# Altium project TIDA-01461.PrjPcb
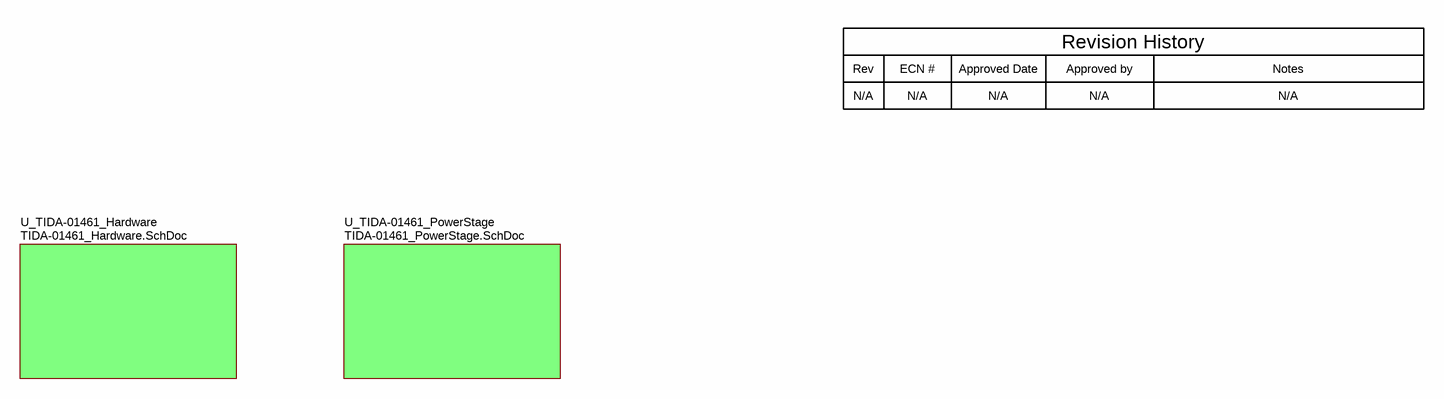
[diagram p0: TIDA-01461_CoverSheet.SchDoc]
CopyrightYear: 2017; PCB_Layout: Tobias Puetz; PCB_Rev: E1; PRJ_Customer: Public Release; PRJ_Engineer: Tobias Puetz; PRJ_Number: TIDA-01461; PRJ_Title: EtherCAT P – One cable for power and EtherCAT Reference Design; SCH_Rev: E1; TechSupport: http://www.ti.com/support; TID: TIDA-01461
6 sheets, 151 parts. Net scope: strictly hierarchical (ports join the sheet entries above them; power ports are local).
Board file: TIDA-01461_PCB.PcbDoc
Sheets:
  TIDA-01461_CoverSheet.SchDoc
    U_TIDA-01461_Hardware = TIDA-01461_Hardware.SchDoc
    U_TIDA-01461_PowerStage = TIDA-01461_PowerStage.SchDoc
      Up = TIDA-01461_PowerInputProtection.SchDoc
      Us = TIDA-01461_PowerInputProtection.SchDoc
      Buck = TIDA-01461_Buck.SchDoc
      TVS3300_Us = TIDA-01461_TVS3300.SchDoc
      TVS3300_Up = TIDA-01461_TVS3300.SchDoc

## Sheet TIDA-01461_CoverSheet.SchDoc: CoverSheet
size 431 x 279 mm; Date: Not shown in title block; ApprovedBy: Not shown in title block; CheckedBy: Not shown in title block; Author: Not shown in title block; CompanyName: Not shown in title block; DrawnBy: Tobias Puetz; Engineer: Not shown in title block; Organization: Not shown in title block; Address1: Not shown in title block; Address2: Not shown in title block; Address3: Not shown in title block; Address4: Not shown in title block; DocumentNumber: 1; Revision: Use project parameter SCH_Rev; SheetNumber: 1; SheetTotal: 6; PageSetup: Record=PageOptions¦CenterHorizontal=True¦CenterVertical=True¦PrintScale=1.00¦XCorrection=1.00¦YCorrection=1.00¦PrintKind=0¦BorderSize=5000000¦LeftOffset=0¦BottomOffset=0¦Orientation=2¦PaperLength=1000¦PaperWidth=1000¦Scale=100¦PaperSource=15¦PrintQuality=600¦MediaType=1¦DitherType=10¦PaperKind=Letter¦PrintScaleMode=1

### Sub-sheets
U_TIDA-01461_Hardware = TIDA-01461_Hardware.SchDoc: no entries
U_TIDA-01461_PowerStage = TIDA-01461_PowerStage.SchDoc: no entries

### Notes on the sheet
- Rev
- N/A
- ECN #
- Approved Date
- Approved by
- Revision History
- Notes

## Sheet TIDA-01461_Hardware.SchDoc: Hardware
size 431 x 279 mm; Date: Not shown in title block; ApprovedBy: Not shown in title block; CheckedBy: Not shown in title block; Author: Not shown in title block; CompanyName: Not shown in title block; DrawnBy: Tobias Puetz; Engineer: Not shown in title block; Organization: Not shown in title block; Address1: Not shown in title block; Address2: Not shown in title block; Address3: Not shown in title block; Address4: Not shown in title block; DocumentNumber: 2; Revision: Use project parameter SCH_Rev; SheetNumber: 2; SheetTotal: 6; PageSetup: Record=PageOptions¦CenterHorizontal=True¦CenterVertical=True¦PrintScale=1.00¦XCorrection=1.00¦YCorrection=1.00¦PrintKind=0¦BorderSize=5000000¦LeftOffset=0¦BottomOffset=0¦Orientation=2¦PaperLength=1000¦PaperWidth=1000¦Scale=100¦PaperSource=15¦PrintQuality=600¦MediaType=1¦DitherType=10¦PaperKind=Letter¦PrintScaleMode=1
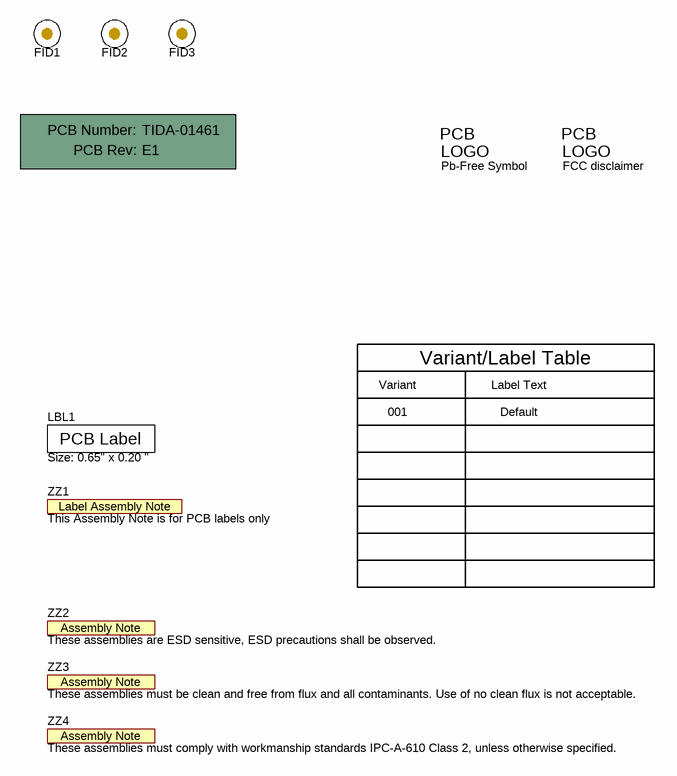
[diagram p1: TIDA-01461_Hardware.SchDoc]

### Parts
!PCB1  Printed Circuit Board  (value not drawn)  (mechanical)
FID1  Fiducial  [Fiducial10-20]  (value not drawn)
FID2  Fiducial  [Fiducial10-20]  (value not drawn)
FID3  Fiducial  [Fiducial10-20]  (value not drawn)
LBL1  Size: 0.65" x 0.20 "  [Label_650x200]
Logo1  Pb-Free Symbol  [Pb-Free_Overlay_Small]  (no BOM)
Logo2  FCC disclaimer  [FCC_disclaimer]  (no BOM)
ZZ1  This Assembly Note is for PCB labels only  [AssemblyNoteLabel]  (no BOM)
ZZ2  These assemblies are ESD sensitive, ESD precautions shall be observed.  [AssemblyNote]  (no BOM)
ZZ3  These assemblies must be clean and free from flux and all contaminants. Use of no clean flux is not acceptable.  [AssemblyNote]  (no BOM)
ZZ4  These assemblies must comply with workmanship standards IPC-A-610 Class 2, unless otherwise specified.  [AssemblyNote]  (no BOM)

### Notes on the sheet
- Variant
- Variant/Label Table
- Label Text
- 001
- Default

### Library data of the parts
!PCB1 = PCB: Manufacturer: Any; PartNumber: TIDA-01461; SymbolCreator: a0412235
FID1-FID3 = Fiducial: Fiducial mark.  There is nothing to buy or mount.; SymbolCreator: codlsc
LBL1 = THT-14-423-10: Thermal Transfer Printable Labels, 0.650" W x 0.200" H - 10,000 per roll; Manufacturer: Brady; SymbolCreator: a0412235; CompType: Label
Logo1 = Pb-Free: SymbolCreator: a0412235
Logo2 = FCC_disclaimer: SymbolCreator: codlsc
ZZ1 = AssemblyNoteLabel: SymbolCreator: a0412235
ZZ2-ZZ4 = AssemblyNote: SymbolCreator: codlsc

## Sheet TIDA-01461_PowerStage.SchDoc: PowerStage
size 431 x 279 mm; Date: Not shown in title block; ApprovedBy: Not shown in title block; CheckedBy: Not shown in title block; Author: Not shown in title block; CompanyName: Not shown in title block; DrawnBy: Tobias Puetz; Engineer: Not shown in title block; Organization: Not shown in title block; Address1: Not shown in title block; Address2: Not shown in title block; Address3: Not shown in title block; Address4: Not shown in title block; DocumentNumber: 3; Revision: Use project parameter SCH_Rev; SheetNumber: 3; SheetTotal: 6; PageSetup: Record=PageOptions¦CenterHorizontal=True¦CenterVertical=True¦PrintScale=1.00¦XCorrection=1.00¦YCorrection=1.00¦PrintKind=0¦BorderSize=5000000¦LeftOffset=0¦BottomOffset=0¦Orientation=2¦PaperLength=1000¦PaperWidth=1000¦Scale=100¦PaperSource=15¦PrintQuality=600¦MediaType=1¦DitherType=10¦PaperKind=Letter¦PrintScaleMode=1
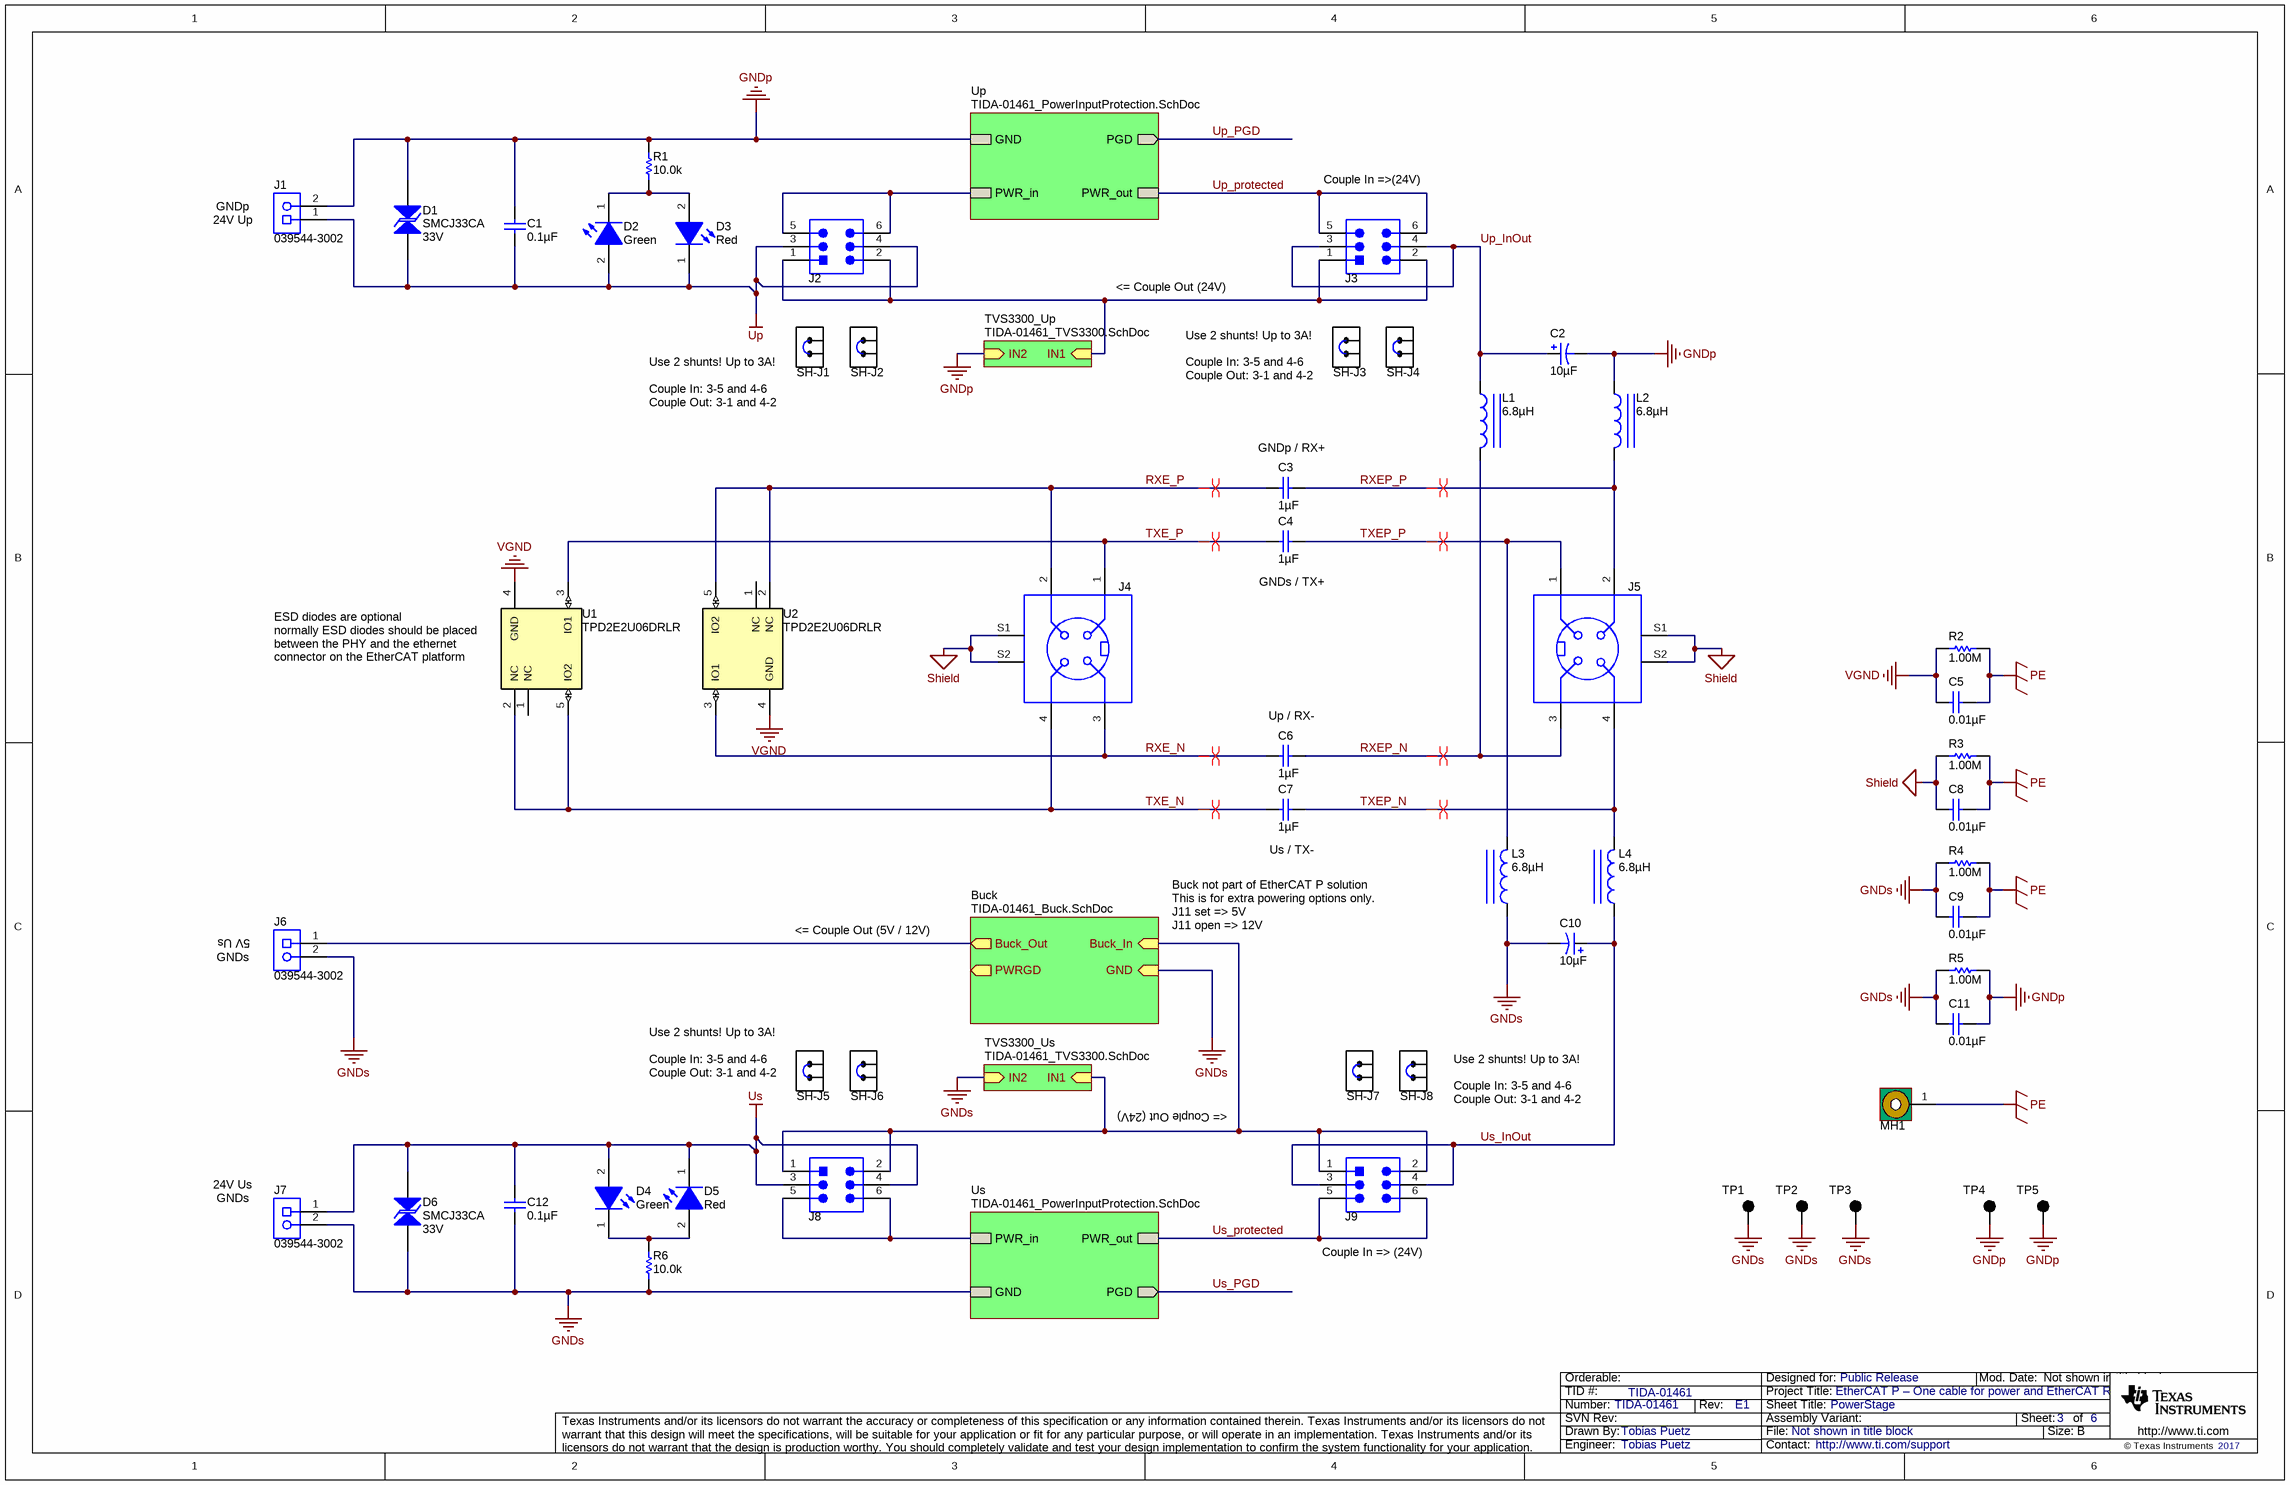
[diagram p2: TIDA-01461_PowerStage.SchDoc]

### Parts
C1  ValueDisplayed: 0.1µF  [1206]  (hidden comment: GRM319R72A104KA01D)
C2  ValueDisplayed: 10µF  [3528-21]  (hidden comment: TCJB106M035R0200)
C3  ValueDisplayed: 1µF  [1206_180]  (hidden comment: GRM31CR72A105KA01L)
C4  ValueDisplayed: 1µF  [1206_180]  (hidden comment: GRM31CR72A105KA01L)
C5  ValueDisplayed: 0.01µF  [1206]  (hidden comment: VJ1206Y103KXEAT5Z)
C6  ValueDisplayed: 1µF  [1206_180]  (hidden comment: GRM31CR72A105KA01L)
C7  ValueDisplayed: 1µF  [1206_180]  (hidden comment: GRM31CR72A105KA01L)
C8  ValueDisplayed: 0.01µF  [1206]  (hidden comment: VJ1206Y103KXEAT5Z)
C9  ValueDisplayed: 0.01µF  [1206]  (hidden comment: VJ1206Y103KXEAT5Z)
C10  ValueDisplayed: 10µF  [3528-21]  (hidden comment: TCJB106M035R0200)
C11  ValueDisplayed: 0.01µF  [1206]  (hidden comment: VJ1206Y103KXEAT5Z)
C12  ValueDisplayed: 0.1µF  [1206]  (hidden comment: GRM319R72A104KA01D)
D1  SMCJ33CA  value 33V  [SMC]
D2  value Green  [WL-SMCW_GREEN]  (hidden comment: 150060GS75000)
D3  value Red  [WL-SMCW_RED]  (hidden comment: 150060RS75000)
D4  value Green  [WL-SMCW_GREEN]  (hidden comment: 150060GS75000)
D5  value Red  [WL-SMCW_RED]  (hidden comment: 150060RS75000)
D6  SMCJ33CA  value 33V  [SMC]
J1  039544-3002  [Molex_039544-3002]
J2  61300621121  [Wurth_61300621121]  (value not drawn)
J3  61300621121  [Wurth_61300621121]  (value not drawn)
J4  09 3420 81 04  [Binder_09_3420_81_04]  (value not drawn)
J5  ZS7002-0001  [Beckhoff_ZS7002-0001]  (value not drawn)
J6  039544-3002  [Molex_039544-3002]
J7  039544-3002  [Molex_039544-3002]
J8  61300621121  [Wurth_61300621121]  (value not drawn)
J9  61300621121  [Wurth_61300621121]  (value not drawn)
L1  ValueDisplayed: 6.8µH  [WE-LHMI_7030]  (hidden comment: 74437346068)
L2  ValueDisplayed: 6.8µH  [WE-LHMI_7030]  (hidden comment: 74437346068)
L3  ValueDisplayed: 6.8µH  [WE-LHMI_7030]  (hidden comment: 74437346068)
L4  ValueDisplayed: 6.8µH  [WE-LHMI_7030]  (hidden comment: 74437346068)
MH1  MTG_Pads  [MTGP_4-40_PanHead]  (value not drawn)  (no BOM)
R1  ValueDisplayed: 10.0k  [0603]  (hidden comment: CRCW060310K0FKEA)
R2  ValueDisplayed: 1.00M  [1206]  (hidden comment: CRCW12061M00FKEA)
R3  ValueDisplayed: 1.00M  [1206]  (hidden comment: CRCW12061M00FKEA)
R4  ValueDisplayed: 1.00M  [1206]  (hidden comment: CRCW12061M00FKEA)
R5  ValueDisplayed: 1.00M  [1206]  (hidden comment: CRCW12061M00FKEA)
R6  ValueDisplayed: 10.0k  [0603]  (hidden comment: CRCW060310K0FKEA)
SH-J1  60900213421  [Wurth_60900213421]  (value not drawn)
SH-J2  60900213421  [Wurth_60900213421]  (value not drawn)
SH-J3  60900213421  [Wurth_60900213421]  (value not drawn)
SH-J4  60900213421  [Wurth_60900213421]  (value not drawn)
SH-J5  60900213421  [Wurth_60900213421]  (value not drawn)
SH-J6  60900213421  [Wurth_60900213421]  (value not drawn)
SH-J7  60900213421  [Wurth_60900213421]  (value not drawn)
SH-J8  60900213421  [Wurth_60900213421]  (value not drawn)
TP1  5001  [Keystone5001]  (value not drawn)
TP2  5001  [Keystone5001]  (value not drawn)
TP3  5001  [Keystone5001]  (value not drawn)
TP4  5001  [Keystone5001]  (value not drawn)
TP5  5001  [Keystone5001]  (value not drawn)
U1  TPD2E2U06DRLR  [DRL0005A]
U2  TPD2E2U06DRLR  [DRL0005A]

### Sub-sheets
Buck = TIDA-01461_Buck.SchDoc: Buck_Out (out), Buck_In (in), GND (in), PWRGD (out)
TVS3300_Up = TIDA-01461_TVS3300.SchDoc: IN2 (in), IN1 (in)
TVS3300_Us = TIDA-01461_TVS3300.SchDoc: IN2 (in), IN1 (in)
Up = TIDA-01461_PowerInputProtection.SchDoc: PGD (out), PWR_in, PWR_out, GND
Us = TIDA-01461_PowerInputProtection.SchDoc: PGD (out), PWR_in, PWR_out, GND

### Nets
GNDp: C1.1 C2.2(-) C11.1 D1.2 J1.2 L2.1 R1.1 R5.2 TP4.1 TP5.1 ; sheet Up/GND, sheet TVS3300_Up/IN2  [project net GND]
GNDs: C9.2 C10.2(-) C11.2 C12.2 D6.1 J6.2 J7.2 L3.1 R4.1 R5.1 R6.2 TP1.1 TP2.1 TP3.1 ; sheet Us/GND, sheet Buck/GND, sheet TVS3300_Us/IN2  [project net GND]
PE: C5.1 C8.1 C9.1 MH1.1 R2.2 R3.2 R4.2
Shield: C8.2 J4.S1 J4.S2 J5.S1 J5.S2 R3.1
Up: C1.2 D1.1 D2.2(A) D3.1(K) J1.1 J2.3 J2.4
Us: C12.1 D4.2(A) D5.1(K) D6.2 J7.1 J8.3 J8.4
VGND: C5.2 R2.1 U1.4(GND) U2.4(GND)
Buck_In: J8.1 J8.2 J9.1 J9.2 ; sheet Buck/Buck_In, sheet TVS3300_Us/IN1
Buck_Out: J6.1 ; sheet Buck/Buck_Out
IN1: J2.1 J2.2 J3.1 J3.2 ; sheet TVS3300_Up/IN1
PWR_in: J8.5 J8.6 ; sheet Us/PWR_in
PWR_in: J2.5 J2.6 ; sheet Up/PWR_in  [a separate net that carries the same name]
RXE_N: C6.2 J4.3 U2.3(IO1)
RXE_P: C3.2 J4.2 U2.2(NC) U2.5(IO2)
RXEP_N: C6.1 J5.3 L1.2
RXEP_P: C3.1 J5.2 L2.2
TXE_N: C7.2 J4.4 U1.2(NC) U1.5(IO2)
TXE_P: C4.2 J4.1 U1.3(IO1)
TXEP_N: C7.1 J5.4 L4.2
TXEP_P: C4.1 J5.1 L3.2
Up_InOut: C2.1(+) J3.3 J3.4 L1.1
Up_protected: J3.5 J3.6 ; sheet Up/PWR_out
Us_InOut: C10.1(+) J9.3 J9.4 L4.1
Us_protected: J9.5 J9.6 ; sheet Us/PWR_out
NetD2_1: D2.1(K) D3.2(A) R1.2
NetD4_1: D4.1(K) D5.2(A) R6.1

Not connected (* = marked no-connect by the designer): U1 1(NC); U2 1(NC)

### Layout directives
differential pair: RXE_N, RXE_P, RXEP_N, RXEP_P, TXE_N, TXE_P, TXEP_N, TXEP_P

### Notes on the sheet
- (near J1) 24V Up
- GNDp
- (near J3) Couple In =>(24V)
- <= Couple Out (24V)
- (near SH-J1) Use 2 shunts! Up to 3A!
  Couple In: 3-5 and 4-6
  Couple Out: 3-1 and 4-2
- (near SH-J3) Use 2 shunts! Up to 3A!
  Couple In: 3-5 and 4-6
  Couple Out: 3-1 and 4-2
- (near C3) GNDp / RX+
- (near C4) GNDs / TX+
- (near U1) ESD diodes are optional
  normally ESD diodes should be placed between the PHY and the ethernet connector on the EtherCAT platform
- (near C6) Up / RX-
- (near C7) Us / TX-
- (near J6) 5V Us
- GNDs
- <= Couple Out (5V / 12V)
- Buck not part of EtherCAT P solution
  This is for extra powering options only.
  J11 set => 5V
  J11 open => 12V
- (near SH-J5) Use 2 shunts! Up to 3A!
  Couple In: 3-5 and 4-6
  Couple Out: 3-1 and 4-2
- (near SH-J8) Use 2 shunts! Up to 3A!
  Couple In: 3-5 and 4-6
  Couple Out: 3-1 and 4-2
- (near J7) 24V Us
- (near J9) Couple In => (24V)

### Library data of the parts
C1 C12 = GRM319R72A104KA01D: CAP, CERM, 0.1 µF, 100 V,+/- 10%, X7R, 1206; Manufacturer: MuRata; Polarized: N; CompType: Capacitor; Value: 0.1uF; U/M: EA; Cap_F: 0.0000001; Tolerance_%: 10; Value1: Unknown; VDC_V: 100; Value2: 100V; TaMin_C: -55; TaMax_C: 125; SizeArea_mm2: 5.12; SizeAreaWB_mm2: 10.92; SizeX_mm: 3.2; SizeY_mm: 1.6; SizeZ_mm: 1.35; AEC Category: Q200
C2 C10 = TCJB106M035R0200: CAP, Tantalum Polymer, 10 µF, 35 V,+/- 20%, 0.2 ohm, 3528-21 SMD; Manufacturer: AVX; Polarized: Y; CompType: Capacitor; Value: 10uF; U/M: EA; Cap_F: 0.00001; Tolerance_%: 20; Value1: 0.2 ohm; VDC_V: 35; Value2: 35V; ESR_ohm: 0.2; IRMS_A: 0.8; TaMin_C: -55; TaMax_C: 105; SizeAreaWB_mm2: 17.1; SizeArea_mm2: 9.8; SizeX_mm: 3.5; SizeY_mm: 2.8; SizeZ_mm: 2.1; AEC Category: Q200; AEC Qualified: N
C3 C4 C6 C7 = GRM31CR72A105KA01L: CAP, CERM, 1 µF, 100 V,+/- 10%, X7R, 1206; Manufacturer: MuRata; Polarized: N; CompType: Capacitor; Value: 1uF; U/M: EA; Cap_F: 0.000001; Tolerance_%: 10; Value1: Unknown; VDC_V: 100; Value2: 100V; TaMin_C: -55; TaMax_C: 125; Cap_Case: 1206; SizeArea_mm2: 5.12; SizeAreaWB_mm2: 10.92; SizeX_mm: 3.2; SizeY_mm: 1.6; SizeZ_mm: 1.8; AEC Category: Q200; Green_Lifecycle: Active; Green_REACh: Passed
C5 C8 C9 C11 = VJ1206Y103KXEAT5Z: CAP, CERM, 0.01 µF, 500 V,+/- 10%, X7R, 1206; Manufacturer: Vishay-Vitramon; Polarized: N; CompType: Capacitor; Value: 0.01uF; U/M: EA; Cap_F: 0.00000001; Tolerance_%: 10; VDC_V: 500; Value2: 500V; TaMin_C: -55; TaMax_C: 125; SizeArea_mm2: 5.12; SizeAreaWB_mm2: 10.92; SizeX_mm: 3.2; SizeY_mm: 1.6; SizeZ_mm: 1.35; AEC Category: Q200
D1 D6 = SMCJ33CA: Diode, TVS, Bi, 33 V, SMC; Manufacturer: Bourns; U/M: EA; Power_W: 5; Vr_V: 33; Value1: 5W; SizeAreaWB_mm2: 83.2686; SizeArea_mm2: 50.5686; SizeX_mm: 8.13; SizeY_mm: 6.22; SizeZ_mm: 2.6; AEC Category: Q101
D2 D4 = 150060GS75000: LED, Green, SMD; Manufacturer: Wurth Elektronik; Type: InGaN; Vf_V: 3.2; Value2: 3.2V; Io_A: 0.02; Tjmax_C: 85; Value1: W; Angle: 140; U/M: EA; Green_Lifecycle: Active; Green_REACh: Passed
D3 D5 = 150060RS75000: LED, Red, SMD; Manufacturer: Wurth Elektronik; Type: AlInGaP; Vf_V: 2; Value2: 2V; Io_A: 0.03; Vr_V: 5; Tjmax_C: 85; Power_TotalModule: 0.072; Value1: 0.072W; Angle: 140; U/M: EA; Green_Lifecycle: Active; Green_REACh: Passed
J1 J6 J7 = 039544-3002: Terminal Block, 5.08mm, 2x1, TH; Manufacturer: Molex; SymbolCreator: a0412235; Pitch_mm: 5.08; Gender: Female; Row_Count: 1; ContactFinish: Tin; Current_A: 15; Voltage_V: 300; Cert_UL: Y
J2 J3 J8 J9 = 61300621121: Header, 2.54mm, 3x2, Gold, TH; Manufacturer: Wurth Elektronik; SymbolCreator: a0412235; Pitch_mm: 2.54; Gender: Male; Shrouded: N; Row_Count: 2; Green_Lifecycle: Active; Green_REACh: Passed
J4 = 09 3420 81 04: M8 Socket, 4Pos, Gold, TH; Manufacturer: Binder-Connector; SymbolCreator: Altium; Gender: Female; Current_A: 4; Voltage_V: 60; Cert_UL: Y
J5 = ZS7002-0001: EtherCAT P, 4 Pos, TH; Manufacturer: Beckhoff; SymbolCreator: Altium; CompType: Socket; Gender: Female; Current_A: 3; Voltage_V: 30
L1-L4 = 74437346068: Inductor, Shielded Drum Core, Powdered Iron, 6.8 µH, 3.4 A, 0.054 ohm, SMD; Manufacturer: Wurth Elektronik; Value: 6.8uH; Ind_H: 6.8E-6; Imax_A: 3.4; Irms: 3.4A @ 40C rise; Isat: 8A @ 20% inductance drop; DCR_ohm: 0.054; Value2: 3.4A; SizeAreaWB_mm2: 73.96; SizeArea_mm2: 43.56; SizeX_mm: 6.6; SizeZ_mm: 3; AEC Category: Q200; AEC Qualified: N; Green_Lifecycle: Active; Green_REACh: Passed
MH1 = Mounting Hole (Imperial) with Pads: PCB Mounting Hole; Manufacturer: Any; SymbolCreator: a0412235
R1 R6 = CRCW060310K0FKEA: RES, 10.0 k, 1%, 0.1 W, 0603; Manufacturer: Vishay-Dale; CompType: Resistor; Value: 10.0k; Res_ohm: 10000; Value_Code: 10k0; Tolerance_%: 1; Power_W: 0.1; Value2: 0.1W; VDC_V: 75; TempCo: 100 ppm/C; SizeArea_mm2: 1.28; SizeX_mm: 1.6; SizeY_mm: 0.8; EIA_Code: E96; U/M: EA; AEC Category: Q200; Green_Lifecycle: Active; Green_REACh: Passed
R2-R5 = CRCW12061M00FKEA: RES, 1.00 M, 1%, 0.25 W, 1206; Manufacturer: Vishay-Dale; CompType: Resistor; Value: 1.00Meg; Res_ohm: 1000000; Value_Code: 1M00; Tolerance_%: 1; Power_W: 0.25; Value2: 0.25W; VDC_V: 200; TempCo: 100 ppm/C; SizeArea_mm2: 5.12; SizeX_mm: 3.2; SizeY_mm: 1.6; SizeZ_mm: 1.35; EIA_Code: E96; U/M: EA; AEC Category: Q200; Green_Lifecycle: Active; Green_REACh: Passed
SH-J1-SH-J8 = 60900213421: Shunt, 2.54mm, Gold, Black; Manufacturer: Wurth Elektronik; Green_Lifecycle: Active; Green_REACh: Passed
TP1-TP5 = 5001: Test Point, Miniature, Black, TH; Manufacturer: Keystone; CompType: Test Point Loop; ContactFinish: Silver; Green_Lifecycle: Active; Green_REACh: Passed
U1 U2 = TPD2E2U06DRLR: Dual-Channel High-Speed ESD Protection, DRL0005A (SOT-OTHER-5); Manufacturer: Texas Instruments; SymbolCreator: a0411947; SizeArea_mm2: 2.56; SizeAreaWB_mm2: 6.76; SizeX_mm: 1.6; SizeZ_mm: 0.6; CompType: IC; U/M: EA; Green_Lifecycle: Active; Green_REACh: Passed

## Sheet TIDA-01461_PowerInputProtection.SchDoc: PowerInputProtection
size 431 x 279 mm; Date: Not shown in title block; ApprovedBy: Not shown in title block; CheckedBy: Not shown in title block; Author: Not shown in title block; CompanyName: Not shown in title block; DrawnBy: Tobias Puetz; Engineer: Not shown in title block; Organization: Not shown in title block; Address1: Not shown in title block; Address2: Not shown in title block; Address3: Not shown in title block; Address4: Not shown in title block; DocumentNumber: 4; Revision: Use project parameter SCH_Rev; SheetNumber: 4; SheetTotal: 6; PageSetup: Record=PageOptions¦CenterHorizontal=True¦CenterVertical=True¦PrintScale=0.66¦XCorrection=1.00¦YCorrection=1.00¦PrintKind=0¦BorderSize=5000000¦LeftOffset=0¦BottomOffset=0¦Orientation=2¦PaperLength=1000¦PaperWidth=1000¦Scale=100¦PaperSource=15¦PrintQuality=600¦MediaType=1¦DitherType=10¦PrintScaleMode=1¦PaperKind=Letter
Used 2 times, as channels U_TIDA-01461_PowerStage/Up, U_TIDA-01461_PowerStage/Us. Parts and nets are listed once, with the designators drawn on the sheet.
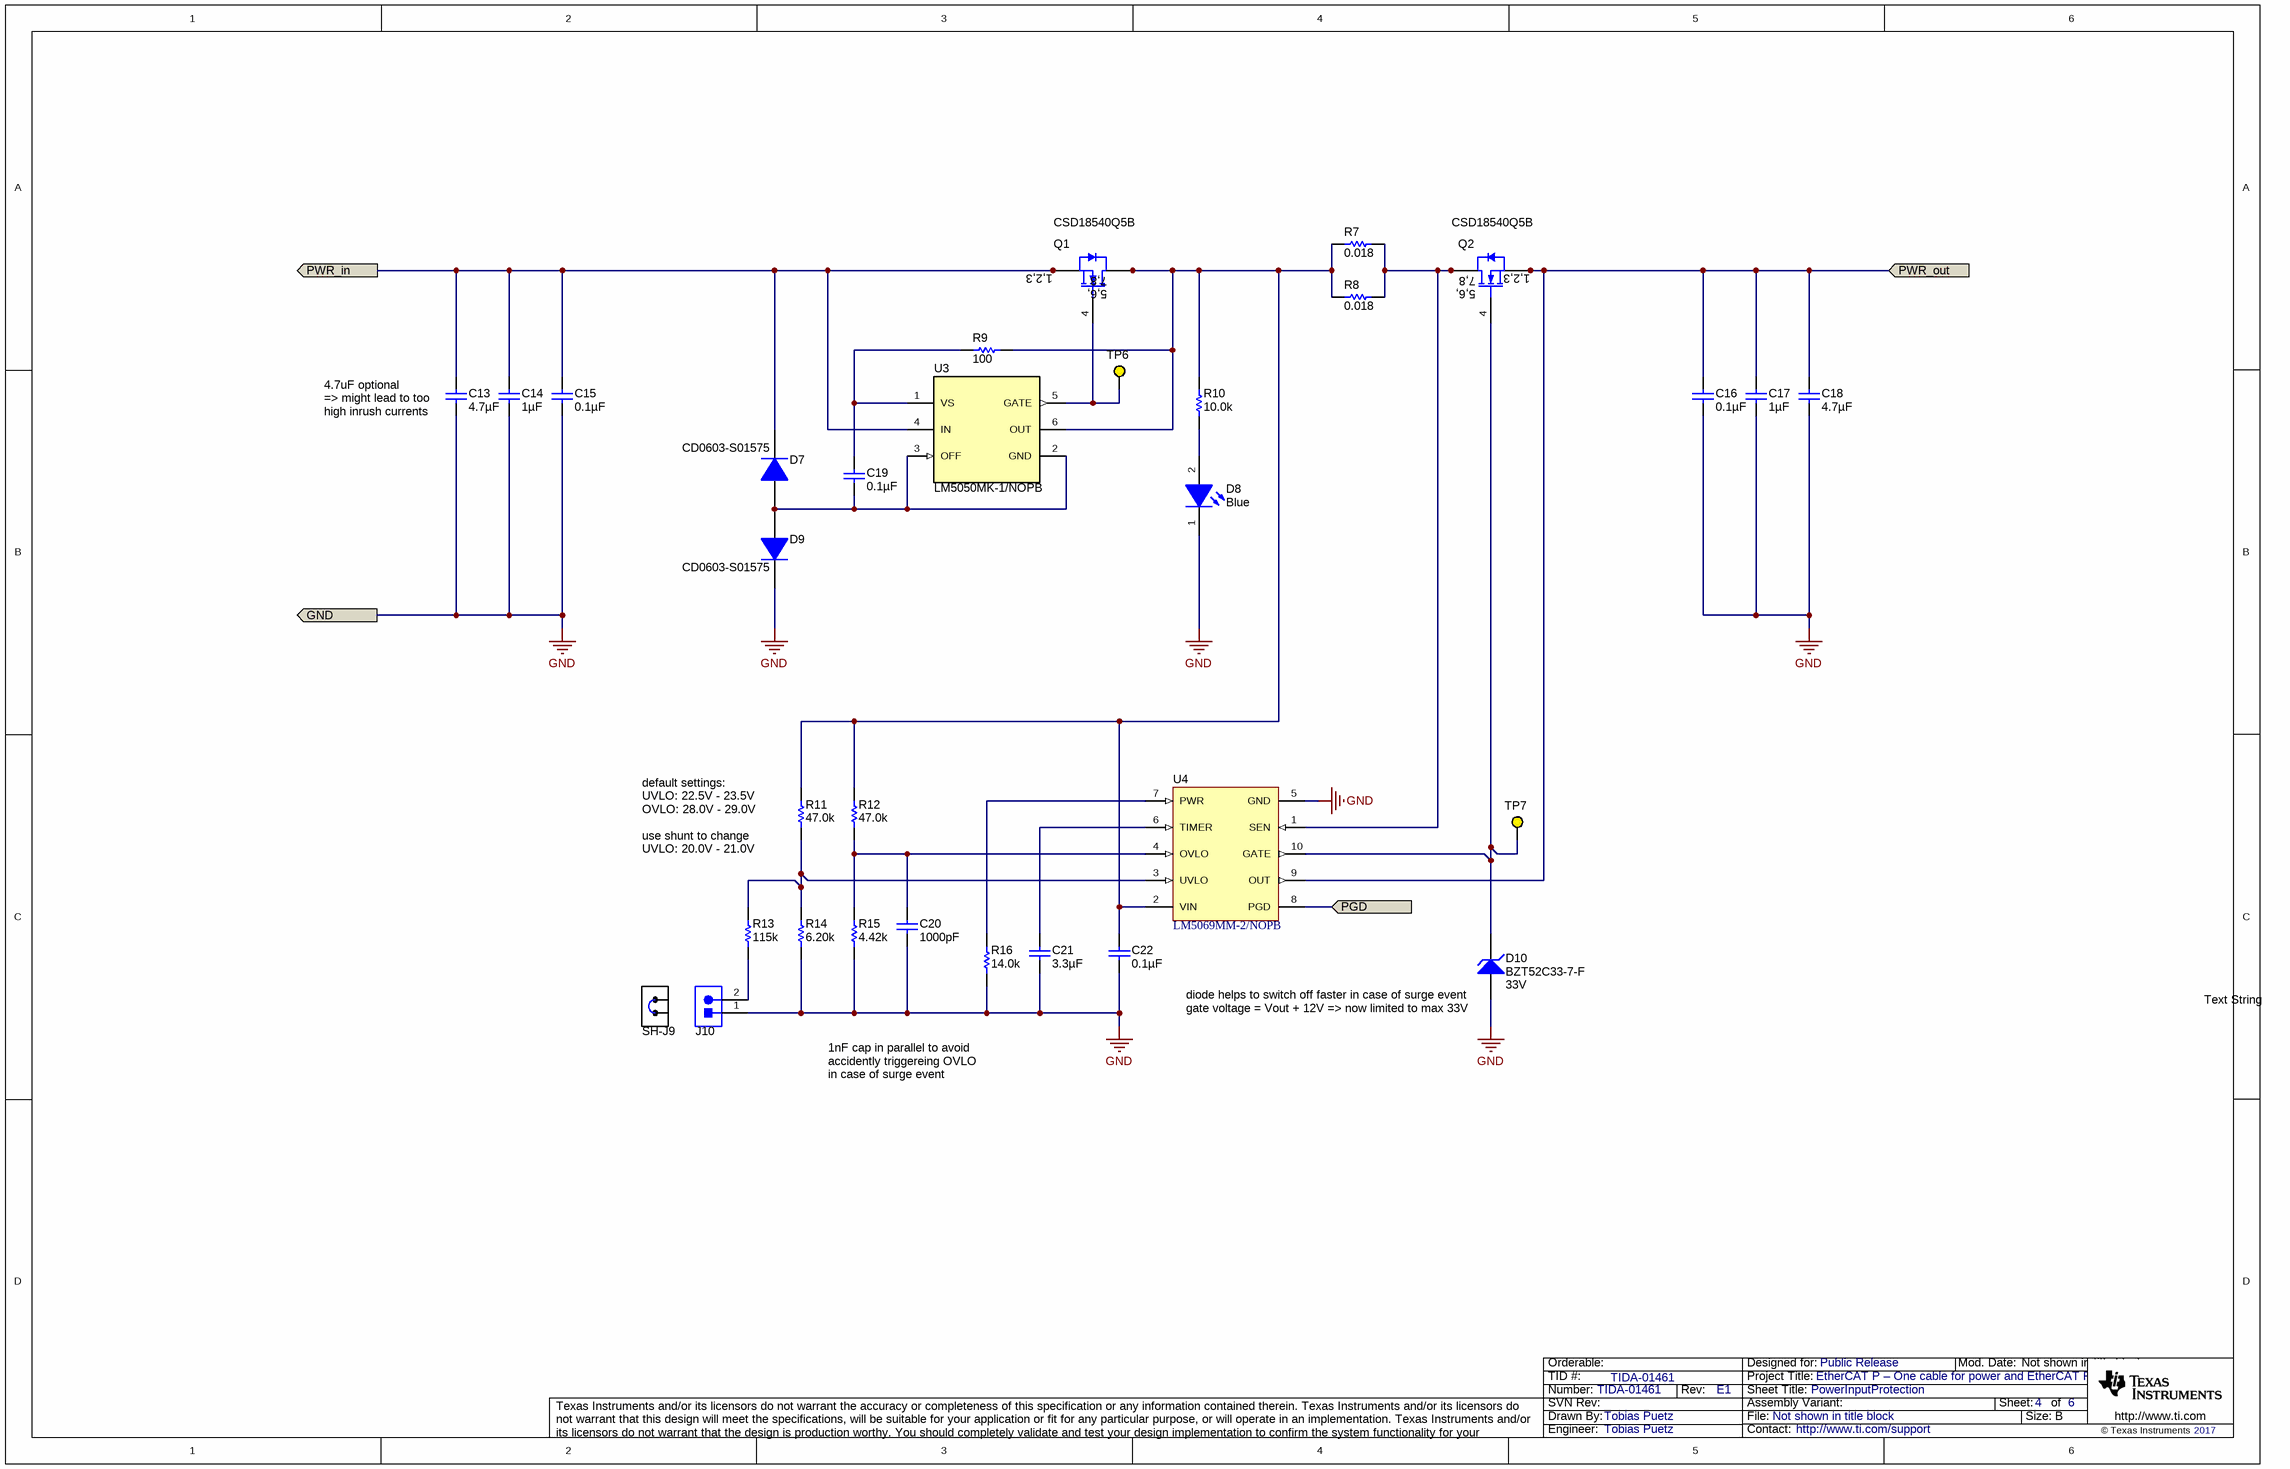
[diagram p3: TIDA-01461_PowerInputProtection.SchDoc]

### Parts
C13  ValueDisplayed: 4.7µF  [1206_180]  (hidden comment: GRM31CR71H475KA12L)
C14  ValueDisplayed: 1µF  [1206_180]  (hidden comment: GRM31CR72A105KA01L)
C15  ValueDisplayed: 0.1µF  [1206L]  (hidden comment: GRM319R72A104KA01D)
C16  ValueDisplayed: 0.1µF  [1206L]  (hidden comment: GRM319R72A104KA01D)
C17  ValueDisplayed: 1µF  [1206_180]  (hidden comment: GRM31CR72A105KA01L)
C18  ValueDisplayed: 4.7µF  [1206_180]  (hidden comment: GRM31CR71H475KA12L)
C19  ValueDisplayed: 0.1µF  [0603]  (hidden comment: GRM188R72A104KA35D)
C20  ValueDisplayed: 1000pF  [0603]  (hidden comment: GRM188R61H102KA01D)
C21  ValueDisplayed: 3.3µF  [0805_HV]  (hidden comment: GRM21BR71C335KA99L)
C22  ValueDisplayed: 0.1µF  [0603]  (hidden comment: 06035C104KAT2A)
D7  CD0603-S01575  [Diode_0603]
D8  value Blue  [WL-SMCW_Blue]  (hidden comment: 150060BS75000)
D9  CD0603-S01575  [Diode_0603]
D10  BZT52C33-7-F  value 33V  [SOD-123]
J10  0022284023  [Molex_0022284023]  (value not drawn)
Q1  CSD18540Q5B  [DNK0008A]
Q2  CSD18540Q5B  [DNK0008A]
R7  ValueDisplayed: 0.018  [KRL1220]  (hidden comment: KRL1220E-M-R018-F-T5)
R8  ValueDisplayed: 0.018  [KRL1220]  (hidden comment: KRL1220E-M-R018-F-T5)
R9  ValueDisplayed: 100  [0603]  (hidden comment: RC0603FR-07100RL)
R10  ValueDisplayed: 10.0k  [0603]  (hidden comment: CRCW060310K0FKEA)
R11  ValueDisplayed: 47.0k  [0603]  (hidden comment: RC0603FR-0747KL)
R12  ValueDisplayed: 47.0k  [0603]  (hidden comment: RC0603FR-0747KL)
R13  ValueDisplayed: 115k  [0603]  (hidden comment: RC0603FR-07115KL)
R14  ValueDisplayed: 6.20k  [0603]  (hidden comment: RC0603FR-076K2L)
R15  ValueDisplayed: 4.42k  [0603]  (hidden comment: RC0603FR-074K42L)
R16  ValueDisplayed: 14.0k  [0603]  (hidden comment: CRCW060314K0FKEA)
SH-J9  60900213421  [Wurth_60900213421]  (value not drawn)
TP6  5004  [Keystone5004]  (value not drawn)
TP7  5004  [Keystone5004]  (value not drawn)
U3  LM5050MK-1/NOPB  [DDC0006A_N]
U4  LM5069MM-2/NOPB  [MUB10A_N]

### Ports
GND, PGD, PWR_in, PWR_out

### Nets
GND: C13.2 C14.2 C15.2 C16.2 C17.2 C18.2 C20.2 C21.2 C22.2 D8.1(K) D9.1(K) D10.2(A) J10.1 R14.1 R15.1 R16.1 U4.5(GND) ; port GND
PGD: U4.8(PGD) ; port PGD
PWR_in: C13.1 C14.1 C15.1 D7.1(K) Q1.1(S) Q1.2(S) Q1.3(S) U3.4(IN) ; port PWR_in
PWR_out: C16.1 C17.1 C18.1 Q2.1(S) Q2.2(S) Q2.3(S) U4.9(OUT) ; port PWR_out
NetC19_1: C19.1 R9.1 U3.1(VS)
NetC19_2: C19.2 D7.2(A) D9.2(A) U3.2(GND) U3.3(OFF)
NetC20_1: C20.1 R12.1 R15.2 U4.4(OVLO)
NetC21_1: C21.1 U4.6(TIMER)
NetC22_1: C22.1 Q1.5(D) Q1.6(D) Q1.7(D) Q1.8(D) Q1.9(D) R7.1 R8.1 R9.2 R10.2 R11.2 R12.2 U3.6(OUT) U4.2(VIN)
NetD8_2: D8.2(A) R10.1
NetD10_1: D10.1(K) Q2.4(G) TP7.1 U4.10(GATE)
NetJ10_2: J10.2 R13.1
NetQ1_4: Q1.4(G) TP6.1 U3.5(GATE)
NetQ2_5: Q2.5(D) Q2.6(D) Q2.7(D) Q2.8(D) Q2.9(D) R7.2 R8.2 U4.1(SEN)
NetR11_1: R11.1 R13.2 R14.2 U4.3(UVLO)
NetR16_2: R16.2 U4.7(PWR)

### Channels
U_TIDA-01461_PowerStage/Up: designators end in _Up; ports GND=GND PGD=Up_PGD PWR_in=PWR_in PWR_out=Up_protected
U_TIDA-01461_PowerStage/Us: designators end in _Us; ports GND=GND PGD=Us_PGD PWR_in=PWR_in PWR_out=Us_protected

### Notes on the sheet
- (near C13) 4.7uF optional
  => might lead to too high inrush currents
- (near R11) default settings:
  UVLO: 22.5V - 23.5V
  OVLO: 28.0V - 29.0V
  use shunt to change
  UVLO: 20.0V - 21.0V
- (near D10) diode helps to switch off faster in case of surge event
  gate voltage = Vout + 12V => now limited to max 33V
- Text String
- 1nF cap in parallel to avoid accidently triggereing OVLO in case of surge event

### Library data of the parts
C13 C18 = GRM31CR71H475KA12L: CAP, CERM, 4.7 µF, 50 V,+/- 10%, X7R, 1206; Manufacturer: MuRata; Polarized: N; CompType: Capacitor; Value: 4.7uF; U/M: EA; Cap_F: 0.0000047; Tolerance_%: 10; Value1: Unknown; VDC_V: 50; Value2: 50V; TaMin_C: -55; TaMax_C: 125; Cap_Case: 1206; SizeArea_mm2: 5.12; SizeAreaWB_mm2: 10.92; SizeX_mm: 3.2; SizeY_mm: 1.6; SizeZ_mm: 1.8; AEC Category: Q200; Green_Lifecycle: Active; Green_REACh: Passed
C14 C17 = GRM31CR72A105KA01L: as C3 on sheet TIDA-01461_PowerStage
C15 C16 = GRM319R72A104KA01D: CAP, CERM, 0.1 µF, 100 V,+/- 10%, X7R, 1206; Manufacturer: MuRata; Polarized: N; CompType: Capacitor; Value: 0.1uF; U/M: EA; Cap_F: 0.0000001; Tolerance_%: 10; Value1: Unknown; VDC_V: 100; Value2: 100V; TaMin_C: -55; TaMax_C: 125; Cap_Case: 1206; SizeArea_mm2: 5.12; SizeAreaWB_mm2: 10.92; SizeX_mm: 3.2; SizeY_mm: 1.6; SizeZ_mm: 1.35; AEC Category: Q200
C19 = GRM188R72A104KA35D: CAP, CERM, 0.1 µF, 100 V,+/- 10%, X7R, 0603; Manufacturer: MuRata; Polarized: N; CompType: Capacitor; Value: 0.1uF; U/M: EA; Cap_F: 0.0000001; Tolerance_%: 10; Value1: Unknown; VDC_V: 100; Value2: 100V; TaMin_C: -55; TaMax_C: 125; SizeArea_mm2: 1.28; SizeAreaWB_mm2: 4.68; SizeX_mm: 1.6; SizeY_mm: 0.8; SizeZ_mm: 1; AEC Category: Q200; Green_Lifecycle: Active; Green_REACh: Passed
C20 = GRM188R61H102KA01D: CAP, CERM, 1000 pF, 50 V,+/- 10%, X5R, 0603; Manufacturer: MuRata; Polarized: N; CompType: Capacitor; Value: 1000pF; U/M: EA; Cap_F: 0.000000001; Tolerance_%: 10; VDC_V: 50; Value2: 50V; TaMin_C: -55; TaMax_C: 85; SizeArea_mm2: 1.28; SizeAreaWB_mm2: 4.68; SizeX_mm: 1.6; SizeY_mm: 0.8; SizeZ_mm: 1; AEC Category: Q200; Green_Lifecycle: Active; Green_REACh: Passed
C21 = GRM21BR71C335KA99L: CAP, CERM, 3.3 µF, 16 V,+/- 10%, X7R, 0805; Manufacturer: MuRata; Polarized: N; CompType: Capacitor; Value: 3.3uF; U/M: EA; Cap_F: 0.0000033; Tolerance_%: 10; VDC_V: 16; Value2: 16V; TaMin_C: -55; TaMax_C: 125; Cap_Case: 0805; SizeArea_mm2: 2.5; SizeAreaWB_mm2: 6.75; SizeX_mm: 2; SizeY_mm: 1.25; SizeZ_mm: 1.45; AEC Category: Q200
C22 = 06035C104KAT2A: CAP, CERM, 0.1 µF, 50 V,+/- 10%, X7R, 0603; Manufacturer: AVX; Polarized: N; CompType: Capacitor; Value: 0.1uF; U/M: EA; Cap_F: 0.0000001; Tolerance_%: 10; Value1: Unknown; VDC_V: 50; Value2: 50V; TaMin_C: -55; TaMax_C: 125; SizeArea_mm2: 1.28; SizeAreaWB_mm2: 4.68; SizeX_mm: 1.6; SizeY_mm: 0.8; SizeZ_mm: 1; AEC Category: Q200; Green_Lifecycle: Active; Green_REACh: Passed
D7 D9 = CD0603-S01575: Diode, Switching, 100 V, 0.15 A, 0603 Diode; Manufacturer: Bourns; U/M: EA; Vf_V: 1; Value: 100V; Value1: 0.15A; Value2: 1V; Io_A: 0.15; Vr_V: 100; TJmax_C: 125; SizeAreaWB_mm2: 5.13; SizeArea_mm2: 1.53; SizeX_mm: 1.7; SizeY_mm: 0.9; SizeZ_mm: 0.75; AEC Category: Q101; Green_Lifecycle: Not Set; Green_REACh: Incomplete
D8 = 150060BS75000: LED, Blue, SMD; Manufacturer: Wurth Elektronik; Type: InGaN; Vf_V: 3.2; Value2: 3.2V; Io_A: 0.03; Vr_V: 5; Tjmax_C: 85; Power_TotalModule: 0.105; Value1: 0.105W; Angle: 140; U/M: EA
D10 = BZT52C33-7-F: Diode, Zener, 33 V, 500 mW, SOD-123; Manufacturer: Diodes Inc.; SymbolCreator: a0412235; U/M: EA; Power_W: 0.5; Vz_V: 33; Value1: 0.5W; RJA_CperW: 338; SizeAreaWB_mm2: 13.095; SizeArea_mm2: 6.545; SizeX_mm: 3.85; SizeY_mm: 1.7; SizeZ_mm: 1.35; AEC Category: Q101; Green_Lifecycle: Active; Green_REACh: Passed
J10 = 0022284023: Header, 2.54mm, 2x1, Tin, TH; Manufacturer: Molex; SymbolCreator: a0412235; Pitch_mm: 2.54; Gender: Male; Shrouded: N; Row_Count: 1; Current_A: 4; Voltage_V: 250; Cert_UL: Y
Q1 Q2 = CSD18540Q5B: MOSFET, N-CH, 60 V, 100 A, DNK0008A (VSON-CLIP-8); Manufacturer: Texas Instruments; Alternate Manufacturer: None; U/M: EA; ChType: N; Value: 60V; VdsMax_V: 60; Value1: 0.0033 ohm; Rdson45_ohm: 0.0033; Value2: 41 nC; QgTyp_nC: 41; Vgs_V: 20; IdsMax_A: 100; SizeAreaWB_mm2: 56; SizeArea_mm2: 30; SizeX_mm: 6; SizeY_mm: 5; SizeZ_mm: 1; AEC Category: Q101
R7 R8 = KRL1220E-M-R018-F-T5: RES, 0.018, 1%, 0.5 W, AEC-Q200 Grade 0, 0805; Manufacturer: Susumu Co Ltd; CompType: Resistor; Value: 0.018; Value_Code: R018; Tolerance_%: 1; Power_W: 0.5; Value2: 0.5W; TempCo: 50 ppm/C; SizeArea_mm2: 2.5; SizeX_mm: 2; SizeY_mm: 1.25; SizeZ_mm: 0.7; EIA_Code: E96; U/M: EA; AEC Category: Q200; AEC Qualified: Y; AEC Grade: 0
R9 = RC0603FR-07100RL: RES, 100, 1%, 0.1 W, 0603; Manufacturer: Yageo America; CompType: Resistor; Value: 100; Value_Code: 100R; Tolerance_%: 1; Power_W: 0.1; Value2: 0.1W; VDC_V: 150; TempCo: 200 ppm/C; SizeArea_mm2: 1.28; SizeX_mm: 1.6; SizeY_mm: 0.8; EIA_Code: E96; U/M: EA; AEC Category: Q200; Green_Lifecycle: Active; Green_REACh: Passed
R10 = CRCW060310K0FKEA: as R1 on sheet TIDA-01461_PowerStage
R11 R12 = RC0603FR-0747KL: RES, 47.0 k, 1%, 0.1 W, 0603; Manufacturer: Yageo America; CompType: Resistor; Value: 47.0k; Res_ohm: 47000; Value_Code: 47k0; Tolerance_%: 1; Power_W: 0.1; Value2: 0.1W; VDC_V: 150; TempCo: 200 ppm/C; SizeArea_mm2: 1.28; SizeX_mm: 1.6; SizeY_mm: 0.8; U/M: EA; AEC Category: Q200; Green_Lifecycle: Active; Green_REACh: Passed
R13 = RC0603FR-07115KL: RES, 115 k, 1%, 0.1 W, 0603; Manufacturer: Yageo America; CompType: Resistor; Value: 115k; Res_ohm: 115000; Tolerance_%: 1; Power_W: 0.1; Value2: 0.1W; VDC_V: 150; TempCo: 200 ppm/C; SizeArea_mm2: 1.28; SizeX_mm: 1.6; SizeY_mm: 0.8; EIA_Code: E96; U/M: EA; AEC Category: Q200
R14 = RC0603FR-076K2L: RES, 6.20 k, 1%, 0.1 W, 0603; Manufacturer: Yageo America; CompType: Resistor; Value: 6.20k; Res_ohm: 6200; Value_Code: 6k20; Tolerance_%: 1; Power_W: 0.1; Value2: 0.1W; VDC_V: 150; TempCo: 200 ppm/C; SizeArea_mm2: 1.28; SizeX_mm: 1.6; SizeY_mm: 0.8; U/M: EA; AEC Category: Q200
R15 = RC0603FR-074K42L: RES, 4.42 k, 1%, 0.1 W, 0603; Manufacturer: Yageo America; CompType: Resistor; Value: 4.42k; Res_ohm: 4420; Value_Code: 4k42; Tolerance_%: 1; Power_W: 0.1; Value2: 0.1W; VDC_V: 150; TempCo: 200 ppm/C; SizeArea_mm2: 1.28; SizeX_mm: 1.6; SizeY_mm: 0.8; EIA_Code: E96; U/M: EA; AEC Category: Q200; Green_Lifecycle: Active; Green_REACh: Passed
R16 = CRCW060314K0FKEA: RES, 14.0 k, 1%, 0.1 W, 0603; Manufacturer: Vishay-Dale; CompType: Resistor; Value: 14.0k; Res_ohm: 14000; Value_Code: 14k0; Tolerance_%: 1; Power_W: 0.1; Value2: 0.1W; VDC_V: 75; TempCo: 100 ppm/C; SizeArea_mm2: 1.28; SizeX_mm: 1.6; SizeY_mm: 0.8; EIA_Code: E96; U/M: EA; AEC Category: Q200; Green_Lifecycle: Active; Green_REACh: Passed
SH-J9 = 60900213421: as SH-J1 on sheet TIDA-01461_PowerStage
TP6 TP7 = 5004: Test Point, Miniature, Yellow, TH; Manufacturer: Keystone; CompType: Test Point Loop; ContactFinish: Silver; Green_Lifecycle: Active; Green_REACh: Passed
U3 = LM5050MK-1/NOPB: High Side OR-ing FET Controller, DDC0006A (SOT-23-T-6); Manufacturer: Texas Instruments; SymbolCreator: Altium; SizeArea_mm2: 4.8675; SizeAreaWB_mm2: 10.4675; SizeX_mm: 1.65; SizeY_mm: 2.95; SizeZ_mm: 0.87; CompType: IC; U/M: EA
U4 = LM5069MM-2/NOPB: Positive High Voltage Hot Swap / Inrush Current Controller with Power Limiting, 10-pin MSOP, Pb-Free; Manufacturer: Texas Instruments; PackageTopMarking: ZXTT*SNBB; PowerWise: N; CompType: MiscPower

## Sheet TIDA-01461_Buck.SchDoc: Buck
size 431 x 279 mm; Date: Not shown in title block; ApprovedBy: Not shown in title block; CheckedBy: Not shown in title block; Author: Not shown in title block; CompanyName: Not shown in title block; DrawnBy: Tobias Puetz; Engineer: Not shown in title block; Organization: Not shown in title block; Address1: Not shown in title block; Address2: Not shown in title block; Address3: Not shown in title block; Address4: Not shown in title block; DocumentNumber: 5; Revision: Use project parameter SCH_Rev; SheetNumber: 5; SheetTotal: 6; PageSetup: Record=PageOptions¦CenterHorizontal=True¦CenterVertical=True¦PrintScale=1.00¦XCorrection=1.00¦YCorrection=1.00¦PrintKind=0¦BorderSize=5000000¦LeftOffset=0¦BottomOffset=0¦Orientation=2¦PaperLength=1000¦PaperWidth=1000¦Scale=100¦PaperSource=15¦PrintQuality=600¦MediaType=1¦DitherType=10¦PaperKind=Letter¦PrintScaleMode=1
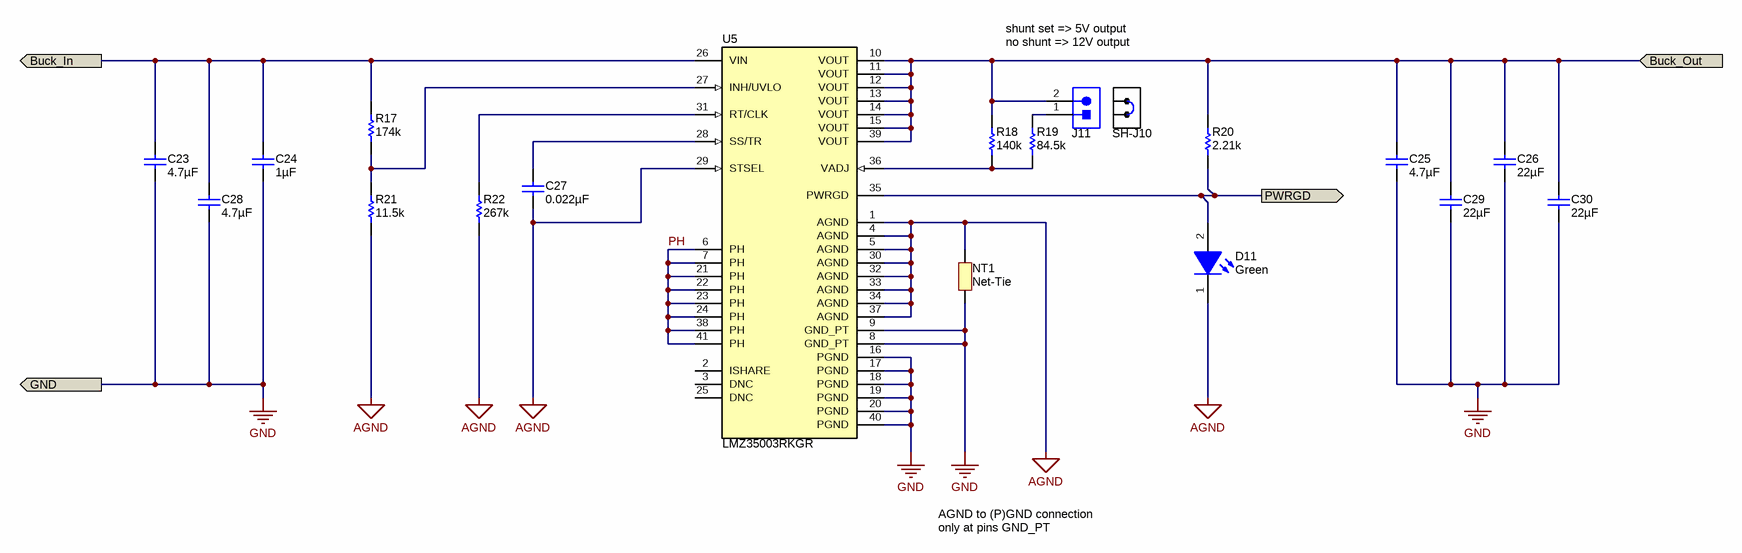
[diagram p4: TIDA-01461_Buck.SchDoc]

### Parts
C23  ValueDisplayed: 4.7µF  [1206_180]  (hidden comment: GRM31CR71H475KA12L)
C24  ValueDisplayed: 1µF  [1206_180]  (hidden comment: GRM31CR72A105KA01L)
C25  ValueDisplayed: 4.7µF  [1206_180]  (hidden comment: GRM31CR71H475KA12L)
C26  ValueDisplayed: 22µF  [1210_280]  (hidden comment: 12103D226MAT2A)
C27  ValueDisplayed: 0.022µF  [0603]  (hidden comment: GRM188R71H223KA01D)
C28  ValueDisplayed: 4.7µF  [1206_180]  (hidden comment: GRM31CR71H475KA12L)
C29  ValueDisplayed: 22µF  [1210_280]  (hidden comment: 12103D226MAT2A)
C30  ValueDisplayed: 22µF  [1210_280]  (hidden comment: 12103D226MAT2A)
D11  value Green  [WL-SMCW_GREEN]  (hidden comment: 150060GS75000)
J11  0022284023  [Molex_0022284023]  (value not drawn)
NT1  Net-Tie  [Net-Tie_10mil]  (net tie, no BOM)
R17  ValueDisplayed: 174k  [0603]  (hidden comment: CRCW0603174KFKEA)
R18  ValueDisplayed: 140k  [0603]  (hidden comment: CRCW0603140KFKEA)
R19  ValueDisplayed: 84.5k  [0603]  (hidden comment: CRCW060384K5FKEA)
R20  ValueDisplayed: 2.21k  [0603]  (hidden comment: CRCW06032K21FKEA)
R21  ValueDisplayed: 11.5k  [0603]  (hidden comment: CRCW060311K5FKEA)
R22  ValueDisplayed: 267k  [0603]  (hidden comment: CRCW0603267KFKEA)
SH-J10  60900213421  [Wurth_60900213421]  (value not drawn)
U5  LMZ35003RKGR  [RKG0041A]

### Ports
Buck_In, Buck_Out, GND, PWRGD (out)

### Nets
AGND: C27.2 D11.1(K) NT1.1 R21.1 R22.1 U5.1(AGND) U5.4(AGND) U5.5(AGND) U5.29(STSEL) U5.30(AGND) U5.32(AGND) U5.33(AGND) U5.34(AGND) U5.37(AGND)
GND: C23.2 C24.1 C25.2 C26.2 C28.2 C29.2 C30.2 NT1.2 U5.8(GND_PT) U5.9(GND_PT) U5.16(PGND) U5.17(PGND) U5.18(PGND) U5.19(PGND) U5.20(PGND) U5.40(PGND) ; port GND
Buck_In: C23.1 C24.2 C28.1 R17.2 U5.26(VIN) ; port Buck_In
Buck_Out: C25.1 C26.1 C29.1 C30.1 J11.2 R18.1 R20.2 U5.10(VOUT) U5.11(VOUT) U5.12(VOUT) U5.13(VOUT) U5.14(VOUT) U5.15(VOUT) U5.39(VOUT) ; port Buck_Out
PH: U5.6(PH) U5.7(PH) U5.21(PH) U5.22(PH) U5.23(PH) U5.24(PH) U5.38(PH) U5.41(PH)
PWRGD: D11.2(A) R20.1 U5.35(PWRGD) ; port PWRGD
NetC27_1: C27.1 U5.28(SS/TR)
NetJ11_1: J11.1 R19.1
NetR17_1: R17.1 R21.2 U5.27(INH/UVLO)
NetR18_2: R18.2 R19.2 U5.36(VADJ)
NetR22_2: R22.2 U5.31(RT/CLK)

Not connected (* = marked no-connect by the designer): U5 2(ISHARE) 3(DNC) 25(DNC)

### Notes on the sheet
- shunt set => 5V output
  no shunt => 12V output
- AGND to (P)GND connection only at pins GND_PT

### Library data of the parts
C23 C25 C28 = GRM31CR71H475KA12L: as C13 on sheet TIDA-01461_PowerInputProtection
C24 = GRM31CR72A105KA01L: as C3 on sheet TIDA-01461_PowerStage
C26 C29 C30 = 12103D226MAT2A: CAP, CERM, 22 µF, 25 V,+/- 20%, X5R, 1210; Manufacturer: AVX; Polarized: N; CompType: Capacitor; Value: 22uF; U/M: EA; Cap_F: 0.000022; Tolerance_%: 20; VDC_V: 25; Value2: 25V; TaMin_C: -55; TaMax_C: 85; Cap_Case: 1210; SizeArea_mm2: 8; SizeAreaWB_mm2: 14.7; SizeX_mm: 3.2; SizeY_mm: 2.5; SizeZ_mm: 2.8; AEC Category: Q200; Green_Lifecycle: Active; Green_REACh: Passed
C27 = GRM188R71H223KA01D: CAP, CERM, 0.022 µF, 50 V,+/- 10%, X7R, 0603; Manufacturer: MuRata; Polarized: N; CompType: Capacitor; Value: 0.022uF; U/M: EA; Cap_F: 0.000000022; Tolerance_%: 10; Value1: Unknown; VDC_V: 50; Value2: 50V; TaMin_C: -55; TaMax_C: 125; SizeArea_mm2: 1.28; SizeAreaWB_mm2: 4.68; SizeX_mm: 1.6; SizeY_mm: 0.8; SizeZ_mm: 1; AEC Category: Q200; Green_Lifecycle: Active; Green_REACh: Passed
D11 = 150060GS75000: as D2 on sheet TIDA-01461_PowerStage
J11 = 0022284023: as J10 on sheet TIDA-01461_PowerInputProtection
NT1 = Net-Tie: Single point connection between nets.; SymbolCreator: codlsc
R17 = CRCW0603174KFKEA: RES, 174 k, 1%, 0.1 W, 0603; Manufacturer: Vishay-Dale; CompType: Resistor; Value: 174k; Res_ohm: 174000; Tolerance_%: 1; Power_W: 0.1; Value2: 0.1W; VDC_V: 75; TempCo: 100 ppm/C; SizeArea_mm2: 1.28; SizeX_mm: 1.6; SizeY_mm: 0.8; EIA_Code: E96; U/M: EA; AEC Category: Q200; Green_Lifecycle: Active; Green_REACh: Passed
R18 = CRCW0603140KFKEA: RES, 140 k, 1%, 0.1 W, 0603; Manufacturer: Vishay-Dale; CompType: Resistor; Value: 140k; Res_ohm: 140000; Tolerance_%: 1; Power_W: 0.1; Value2: 0.1W; VDC_V: 75; TempCo: 100 ppm/C; SizeArea_mm2: 1.28; SizeX_mm: 1.6; SizeY_mm: 0.8; EIA_Code: E96; U/M: EA; AEC Category: Q200; Green_Lifecycle: Active; Green_REACh: Passed
R19 = CRCW060384K5FKEA: RES, 84.5 k, 1%, 0.1 W, 0603; Manufacturer: Vishay-Dale; CompType: Resistor; Value: 84.5k; Res_ohm: 84500; Value_Code: 84k5; Tolerance_%: 1; Power_W: 0.1; Value2: 0.1W; VDC_V: 75; TempCo: 100 ppm/C; SizeArea_mm2: 1.28; SizeX_mm: 1.6; SizeY_mm: 0.8; EIA_Code: E96; U/M: EA; AEC Category: Q200; Green_Lifecycle: Active; Green_REACh: Passed
R20 = CRCW06032K21FKEA: RES, 2.21 k, 1%, 0.1 W, 0603; Manufacturer: Vishay-Dale; CompType: Resistor; Value: 2.21k; Res_ohm: 2210; Value_Code: 2k21; Tolerance_%: 1; Power_W: 0.1; Value2: 0.1W; VDC_V: 75; TempCo: 100 ppm/C; SizeArea_mm2: 1.28; SizeX_mm: 1.6; SizeY_mm: 0.8; EIA_Code: E96; U/M: EA; AEC Category: Q200; Green_Lifecycle: Active; Green_REACh: Passed
R21 = CRCW060311K5FKEA: RES, 11.5 k, 1%, 0.1 W, 0603; Manufacturer: Vishay-Dale; CompType: Resistor; Value: 11.5k; Res_ohm: 11500; Value_Code: 11k5; Tolerance_%: 1; Power_W: 0.1; Value2: 0.1W; VDC_V: 75; TempCo: 100 ppm/C; SizeArea_mm2: 1.28; SizeX_mm: 1.6; SizeY_mm: 0.8; EIA_Code: E96; U/M: EA; AEC Category: Q200; Green_Lifecycle: Active; Green_REACh: Passed
R22 = CRCW0603267KFKEA: RES, 267 k, 1%, 0.1 W, 0603; Manufacturer: Vishay-Dale; CompType: Resistor; Value: 267k; Res_ohm: 267000; Tolerance_%: 1; Power_W: 0.1; Value2: 0.1W; VDC_V: 75; TempCo: 100 ppm/C; SizeArea_mm2: 1.28; SizeX_mm: 1.6; SizeY_mm: 0.8; EIA_Code: E96; U/M: EA; AEC Category: Q200; Green_Lifecycle: Active; Green_REACh: Passed
SH-J10 = 60900213421: as SH-J1 on sheet TIDA-01461_PowerStage
U5 = LMZ35003RKGR: SIMPLE SWITCHER(R) 7V to 50V, 2.5A Wide Vin Power Module in Small Package, RKG0041A (B1QFN-41); Alternate PartNumber: LMZ35003RKGT; Manufacturer: Texas Instruments; SymbolCreator: a0799628; SizeArea_mm2: 99; SizeAreaWB_mm2: 143; SizeX_mm: 9; SizeY_mm: 11; SizeZ_mm: 2.9; CompType: IC; U/M: EA

## Sheet TIDA-01461_TVS3300.SchDoc: TVS3300
size 431 x 279 mm; Date: Not shown in title block; ApprovedBy: Not shown in title block; CheckedBy: Not shown in title block; Author: Not shown in title block; CompanyName: Not shown in title block; DrawnBy: Tobias Puetz; Engineer: Not shown in title block; Organization: Not shown in title block; Address1: Not shown in title block; Address2: Not shown in title block; Address3: Not shown in title block; Address4: Not shown in title block; DocumentNumber: 6; Revision: Use project parameter SCH_Rev; SheetNumber: 6; SheetTotal: 6; PageSetup: Record=PageOptions¦CenterHorizontal=True¦CenterVertical=True¦PrintScale=1.00¦XCorrection=1.00¦YCorrection=1.00¦PrintKind=0¦BorderSize=5000000¦LeftOffset=0¦BottomOffset=0¦Orientation=2¦PaperLength=1000¦PaperWidth=1000¦Scale=100¦PaperSource=15¦PrintQuality=600¦MediaType=1¦DitherType=10¦PaperKind=Letter¦PrintScaleMode=1
Used 2 times, as channels U_TIDA-01461_PowerStage/TVS3300_Us, U_TIDA-01461_PowerStage/TVS3300_Up. Parts and nets are listed once, with the designators drawn on the sheet.
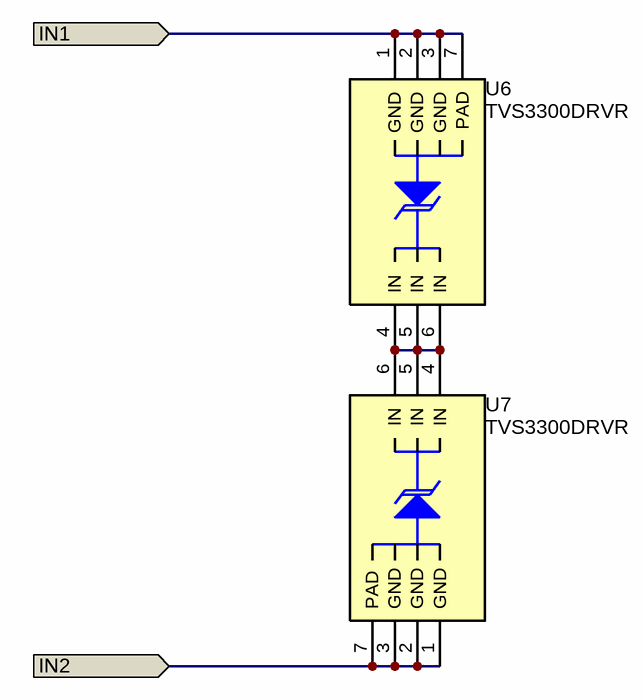
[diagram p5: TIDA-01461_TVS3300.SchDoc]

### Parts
U6  TVS3300DRVR  [DRV0006A]
U7  TVS3300DRVR  [DRV0006A]

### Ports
IN1 (in), IN2 (in)

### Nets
IN1: U6.1(GND) U6.2(GND) U6.3(GND) U6.7(PAD) ; port IN1
IN2: U7.1(GND) U7.2(GND) U7.3(GND) U7.7(PAD) ; port IN2
NetU6_4: U6.4(IN) U6.5(IN) U6.6(IN) U7.4(IN) U7.5(IN) U7.6(IN)

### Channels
U_TIDA-01461_PowerStage/TVS3300_Us: designators end in _TVS3300_Us; ports IN1=Buck_In IN2=GND
U_TIDA-01461_PowerStage/TVS3300_Up: designators end in _TVS3300_Up; ports IN1=IN1 IN2=GND

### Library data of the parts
U6 U7 = TVS3300DRVR: 33V Precision Surge Protection Clamp, DRV0006A (WSON-6); Alternate PartNumber: TVS3300DRVT; Manufacturer: Texas Instruments; SymbolCreator: Altium; SizeArea_mm2: 4; SizeAreaWB_mm2: 9; SizeX_mm: 2; SizeZ_mm: 0.8; CompType: IC; U/M: EA

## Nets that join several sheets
GND: TIDA-01461_PowerStage (14 pins), U_TIDA-01461_PowerStage/Us (17 pins), TIDA-01461_Buck (16 pins), U_TIDA-01461_PowerStage/TVS3300_Us (U7_TVS3300_Us.1 U7_TVS3300_Us.2 U7_TVS3300_Us.3 U7_TVS3300_Us.7)
GND: TIDA-01461_PowerStage (10 pins), U_TIDA-01461_PowerStage/Up (17 pins), U_TIDA-01461_PowerStage/TVS3300_Up (U7_TVS3300_Up.1 U7_TVS3300_Up.2 U7_TVS3300_Up.3 U7_TVS3300_Up.7)
Buck_In: TIDA-01461_PowerStage (J8.1 J8.2 J9.1 J9.2), TIDA-01461_Buck (5 pins), U_TIDA-01461_PowerStage/TVS3300_Us (U6_TVS3300_Us.1 U6_TVS3300_Us.2 U6_TVS3300_Us.3 U6_TVS3300_Us.7)
Buck_Out: TIDA-01461_PowerStage (J6.1), TIDA-01461_Buck (14 pins)
IN1: TIDA-01461_PowerStage (J2.1 J2.2 J3.1 J3.2), U_TIDA-01461_PowerStage/TVS3300_Up (U6_TVS3300_Up.1 U6_TVS3300_Up.2 U6_TVS3300_Up.3 U6_TVS3300_Up.7)
PWR_in: TIDA-01461_PowerStage (J8.5 J8.6), U_TIDA-01461_PowerStage/Us (8 pins)
PWR_in: TIDA-01461_PowerStage (J2.5 J2.6), U_TIDA-01461_PowerStage/Up (8 pins)
Up_protected: TIDA-01461_PowerStage (J3.5 J3.6), U_TIDA-01461_PowerStage/Up (7 pins)
Us_protected: TIDA-01461_PowerStage (J9.5 J9.6), U_TIDA-01461_PowerStage/Us (7 pins)

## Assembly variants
001: not fitted C13_Up C13_Us R8_Up R8_Us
